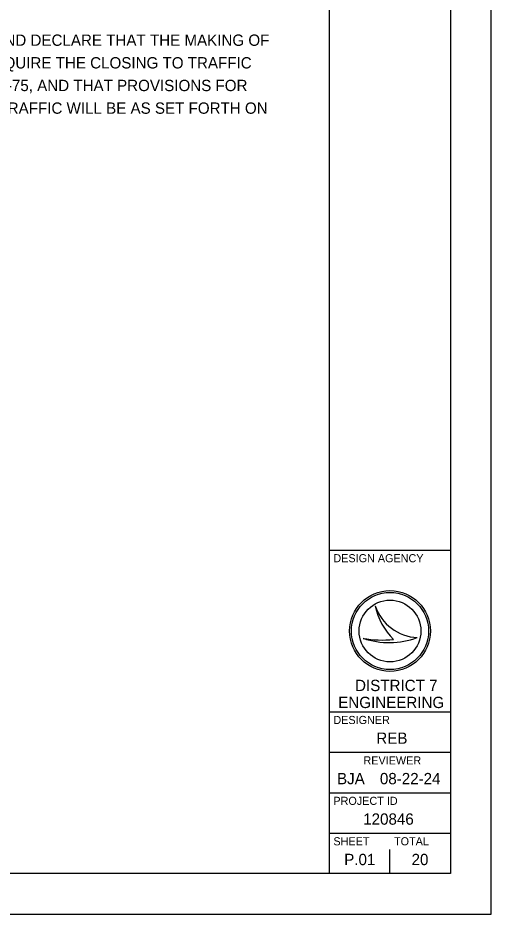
# Model space of a CAD drawing. Extents: x 0 to 34, y 0 to 22.
# Drawn here: x 28.15 to 34, y 0 to 11.08 of the extents above; entities that cross this region are included whole.
import ezdxf

# ---------------------------------------------------------------- set-up
doc = ezdxf.new("R2010")
doc.units = 0
for name, color, linetype in [('SH_Border', 7, 'Continuous'), ('SH_Cut_Line', 7, 'Continuous'), ('SH_Data', 7, 'Continuous'), ('SH_Text', 7, 'Continuous')]:
    doc.layers.add(name, color=color, linetype=linetype)

msp = doc.modelspace()

# ---------------------------------------------------------------- linework, layer by layer
at = {"layer": 'SH_Border'}
for p, q in [((32, 0.5), (32, 21.5)), ((32, 4.5), (33.5, 4.5)), ((32, 2.5), (33.5, 2.5)), ((32, 2), (33.5, 2)), ((32, 1.5), (33.5, 1.5)), ((32, 1), (33.5, 1))]:
    msp.add_line(p, q, dxfattribs=at)
msp.add_lwpolyline([(1.5, 21.5), (33.5, 21.5), (33.5, 0.5), (1.5, 0.5)], close=True, dxfattribs=at)
at = {"layer": 'SH_Cut_Line'}
msp.add_lwpolyline([(0, 0), (34, 0), (34, 22), (0, 22)], close=True, dxfattribs=at)
at = {"layer": 'SH_Data'}
for p, q in [((32.567, 3.81), (32.567, 3.81)), ((32.75, 3.5), (32.75, 3.5)), ((32.417, 3.41), (32.417, 3.41)), ((33.087, 3.419), (33.087, 3.419)), ((32.75, 0.5), (32.75, 0.8)), ((32.375, 0.675), (32.375, 0.675))]:
    msp.add_line(p, q, dxfattribs=at)
for radius in [0.5, 0.477, 0.477, 0.382]:
    msp.add_circle((32.75, 3.5), radius, dxfattribs=at)
for centre, radius, start, end in [((33.116, 3.998), 0.58, 198.9257, 198.9319), ((33.347, 3.97), 0.796, 191.6379, 191.6421), ((33.116, 3.998), 0.58, 198.9319, 267.1657), ((33.347, 3.97), 0.796, 191.6421, 226.0947), ((32.739, 4.37), 1.013, 251.4576, 290.0832), ((32.648, 4.654), 1.266, 259.4964, 259.4995), ((32.739, 4.37), 1.013, 251.4527, 251.4576), ((32.648, 4.654), 1.266, 259.4995, 276.6672)]:
    msp.add_arc(centre, radius, start, end, dxfattribs=at)

# ---------------------------------------------------------------- texts
for s, height, p in [('DESIGN AGENCY', 0.1, (32.05, 4.35)), ('DESIGNER', 0.1, (32.05, 2.35)), ('REB', 0.14, (32.581, 2.105)), ('REVIEWER', 0.1, (32.422, 1.85)), ('BJA', 0.14, (32.095, 1.605)), ('08-22-24', 0.14, (32.625, 1.605)), ('PROJECT ID', 0.1, (32.05, 1.35)), ('120846', 0.14, (32.419, 1.105)), ('SHEET', 0.1, (32.05, 0.85)), ('TOTAL', 0.1, (32.8, 0.85)), ('P.01', 0.14, (32.184, 0.605)), ('20', 0.14, (33.017, 0.605))]:
    msp.add_text(s, height=height, dxfattribs=at).set_placement(p)
at = {"layer": 'SH_Text'}
for s, p in [('  I HEREBY APPROVE THESE PLANS AND DECLARE THAT THE MAKING OF ', (24.528, 10.735)), ('THESE IMPROVEMENTS WILL NOT REQUIRE THE CLOSING TO TRAFFIC', (24.528, 10.455)), ('OF THE HIGHWAY FOR CLA-70 OR MIA-75, AND THAT PROVISIONS FOR', (24.528, 10.175)), ('THE MAINTENANCE AND SAFETY OF TRAFFIC WILL BE AS SET FORTH ON', (24.528, 9.895)), ('    DISTRICT 7 ', (32.11, 2.757)), ('ENGINEERING', (32.11, 2.547))]:
    msp.add_text(s, height=0.14, dxfattribs=at).set_placement(p)

doc.saveas('drawing.dxf')
